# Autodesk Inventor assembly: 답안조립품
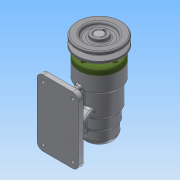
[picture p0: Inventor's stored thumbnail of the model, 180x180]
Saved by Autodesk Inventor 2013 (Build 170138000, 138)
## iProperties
Created: 2016-06
Part Number: 답안조립품
Document SubType Name: Assembly
Designer: Administrator
Author: Administrator
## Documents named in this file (12)
- C:\Users\Administrator\Desktop\460608V1020\답안조립품.iam
- C:\Users\Administrator\Desktop\460608V1020\V벨트풀리.ipt
- C:\Users\Administrator\Desktop\460608V1020\멈춤나사 M3x8.ipt
- C:\Users\Administrator\Desktop\460608V1020\베어링 6004.ipt
- C:\Users\Administrator\Desktop\460608V1020\베어링 51202.ipt
- C:\Users\Administrator\Desktop\460608V1020\본체.ipt
- C:\Users\Administrator\Desktop\460608V1020\볼트 M4 x 12.ipt
- C:\Users\Administrator\Desktop\460608V1020\어댑터슬리브.ipt
- C:\Users\Administrator\Desktop\460608V1020\오일 실.ipt
- C:\Users\Administrator\Desktop\460608V1020\축.ipt
- C:\Users\Administrator\Desktop\460608V1020\커버.ipt
- C:\Users\Administrator\Desktop\460608V1020\키 5 x 5 x 16.ipt
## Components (2 placed, 2 different names)
1. V벨트풀리:1
2. ISO 4762 M4 x 12:1
